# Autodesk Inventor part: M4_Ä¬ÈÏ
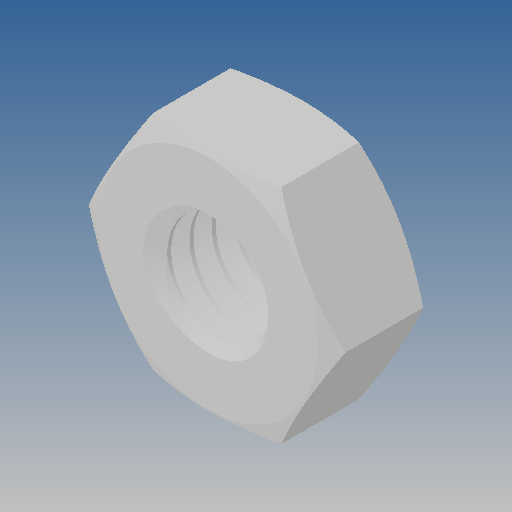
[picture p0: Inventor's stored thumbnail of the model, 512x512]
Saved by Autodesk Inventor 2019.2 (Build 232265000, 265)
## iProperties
Created: 2010-06
Part Number: M4_Ä¬ÈÏ
Material: Ogólny
Document SubType Name: Modeling
Designer: CADENGINEERING4
Density: 1 g/cm^3
Appearance: Domyślna
Author: CADENGINEERING4
Revision Number: ÈÎºÎ
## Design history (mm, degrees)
feature "NONE"
node "Bryła1"
